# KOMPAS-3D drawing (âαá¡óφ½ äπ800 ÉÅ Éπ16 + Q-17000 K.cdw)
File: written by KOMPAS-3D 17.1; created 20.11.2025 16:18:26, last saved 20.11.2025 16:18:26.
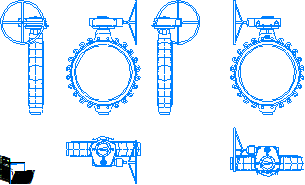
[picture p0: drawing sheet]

Sheet 1: A4, portrait

Title block, sheet 1: name: Гранвел Ду800; material: Сталь 10  ГОСТ 1050-88; mass: 652,7; sheets: 1; sheet format: A4

Views: Проекционный вид 2, Проекционный вид 3, Проекционный вид 4, Проекционный вид 5, Проекционный вид 6
Referenced files in \\adlc.lan\data\АДЛ_ПКД\3D-модели\ADL production\Дисковые поворотные затворы ГРАНВЭЛ\с резьбовыми проушинами с китайским редуктором Ру 16\KOMPAS 3D\: Гранвэл Ду800 РП Ру16 + Q-17000 K.m3d
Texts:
  Andrey
  АДЛ
Dimensions and other numbers on the sheet: 1:1; 1; 652,7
